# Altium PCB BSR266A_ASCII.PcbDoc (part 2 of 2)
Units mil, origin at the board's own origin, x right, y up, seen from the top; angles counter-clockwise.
Board outline 1624.02 x 1771.65 mil, 4 copper layers (Top Layer, GND 01, GND 02, Bottom Layer), stack 60.4 mil thick; 39 components, 9 nets, 52 pads, 271 vias.
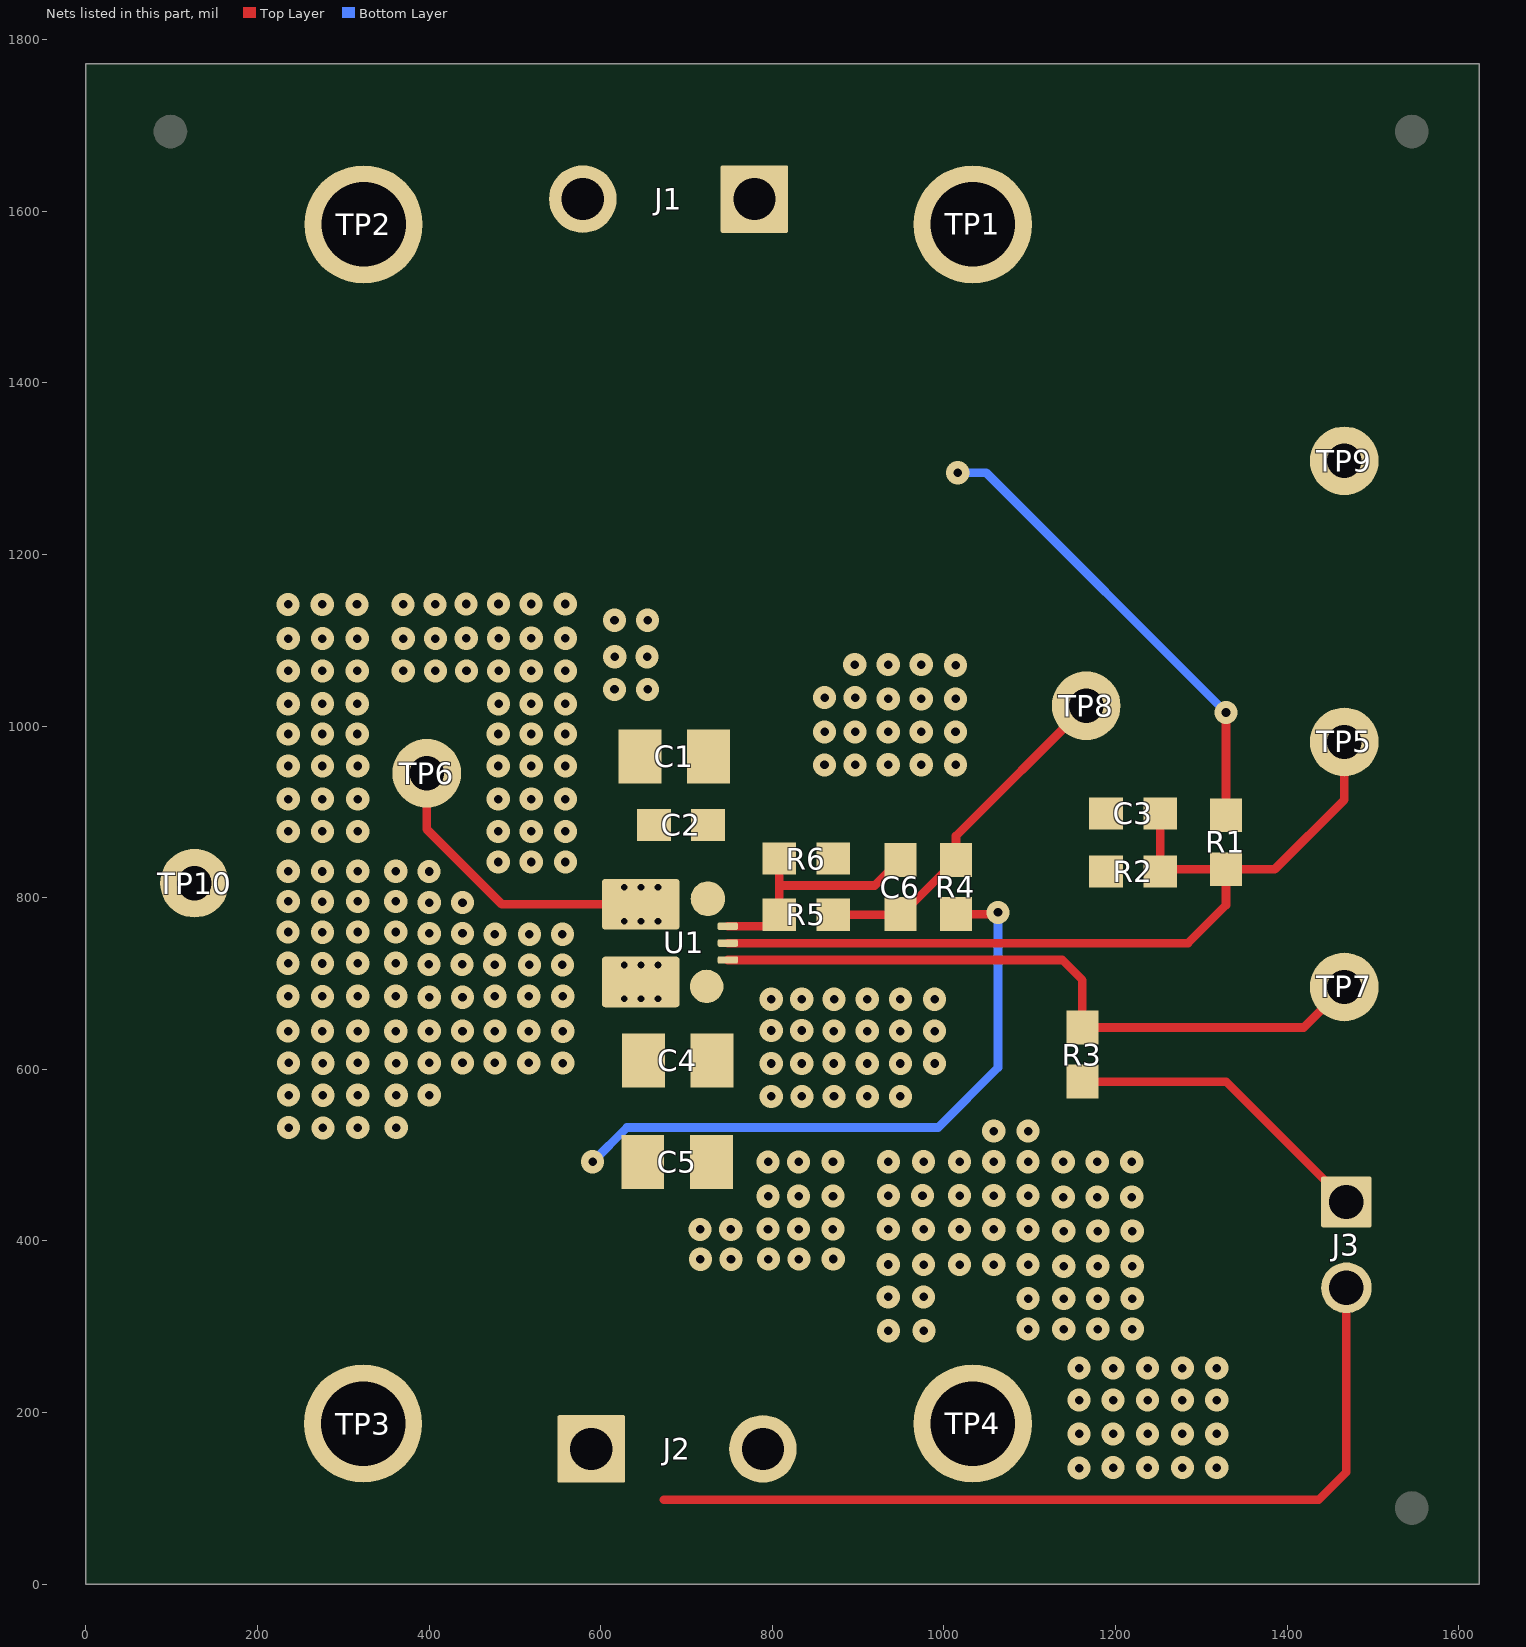
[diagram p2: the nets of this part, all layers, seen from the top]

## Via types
v1: diameter 27, hole 10, Top Layer to Bottom Layer, 259 vias
v2: diameter 19.68, hole 7.87, Top Layer to Bottom Layer, 12 vias

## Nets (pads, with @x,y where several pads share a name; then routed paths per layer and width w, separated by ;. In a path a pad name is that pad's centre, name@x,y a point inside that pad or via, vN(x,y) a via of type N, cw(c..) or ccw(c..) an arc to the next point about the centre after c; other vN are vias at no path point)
EN: C3.1 R1.1 R2.2 TP5.1 U1.6 | length 1025
  Top Layer w10: U1.6@748.03,747.03 1284.45,747.03 1328.68,791.27 R1.1@1328.68,833.01 ; C3.1@1251.97,898.2 R2.2@1251.97,830.56 1254.42,833.01 R1.1@1328.68,833.01 ; TP5.1@1466.54,981.48 1466.54,913.96 1385.59,833.01 R1.1@1328.68,833.01
FB: C6.2 R5.1 R6.2 U1.7 | length 295.7
  Top Layer w10: U1.7@748.03,766.71 794.67,766.71 R5.1@808.05,780.09 808.05,814.15 ; R5.1@799.97,766.71 R5.1@808.05,774.78 ; R6.2@808.05,845.47 808.05,814.15 ; C6.2@949.12,843.81 919.46,814.15 808.05,814.15
GND: C1.2 C2.2 C3.2 C4.2 C5.2 J1.2 J2.2 R2.1 R6.1 TP2.1 TP4.1 TP9.1 TP10.1 U1.4
  other v1: 1157.46,135.1 1197.18,135.65 1237.29,135.65 1277.84,135.65 1317.96,135.65 1157.46,175.02 1197.18,175.02 1237.29,175.02 1277.84,175.02 1317.96,175.02 1157.46,214.39 1197.18,214.39 1237.29,214.39 1277.84,214.39 1317.96,214.39 1157.46,251.67 1197.18,251.67 1237.29,251.67 1277.84,251.67 1317.96,251.67 935.3,295.28 976.58,295.28 1098.13,297.07 1139.52,297.07 1179.24,297.07 1219.36,297.07 1098.13,332.68 1139.52,332.68 1179.24,332.68 1219.36,332.68 935.04,334.65 976.32,334.65 1139.52,370.39 1179.24,370.39 1219.36,370.39 935.04,372.39 976.32,372.36 1018.29,372.36 1058.01,372.36 1098.13,372.36 716.13,378.49 751.8,378.49 795.31,378.74 830.99,378.74 871,378.82 1139.52,411.42 1179.24,411.42 1219.36,411.42 715.75,413.39 751.42,413.39 976.32,413.39 1018.29,413.39 1058.01,413.39 1098.13,413.39 794.93,413.64 830.6,413.64 870.61,413.72 935.04,413.69 1138.96,451.02 1178.69,451.02 1218.8,451.02 794.98,452.04 830.6,452.04 870.66,452.12 935.3,452.76 975.03,452.76 1018.29,452.76 1058.01,452.76 1098.13,452.76 794.98,492.04 830.6,492.04 870.66,492.13 935.3,492.13 976.32,492.13 1018.29,492.13 1058.01,492.13 1098.13,492.13 1138.96,492.04 1178.69,492.04 1218.8,492.04 1058.01,527.83 1098.13,527.83 236.14,531.96 276.12,531.69 316.69,531.96 361.57,531.96 798.69,568.36 834.37,568.36 871.81,568.36 910.7,568.36 949.18,568.36 236.14,569.87 276.12,569.59 316.69,569.87 361.57,569.7 400.07,569.87 236.14,607.33 276.12,607.06 316.69,607.33 361.57,607.17 400.07,607.33 438.83,607.33 476.63,607.33 516.06,607.33 555.68,607.17 798.64,606.72 834.31,606.72 871.76,606.72 910.65,606.72 949.18,606.72 989.17,606.72 235.61,644.49 275.59,644.21 316.69,644.49 361.04,644.32 400.07,644.49 438.83,644.49 476.63,644.49 516.06,644.49 555.68,644.32 871.76,644.49 910.65,644.49 949.18,644.49 989.17,644.49 798.69,645.12 834.31,645.12 798.69,681.58 834.31,681.58 871.94,681.58 910.65,681.58 949.18,681.58 989.17,681.58 400.07,683.88 438.83,683.88 235.61,685.16 275.59,684.89 316.69,685.16 361.04,685.16 476.63,685.16 516.06,685.16 555.68,685.16 399.71,722.2 438.46,722.2 476.27,721.68 516.79,721.68 555.32,721.68 235.61,723.47 275.59,723.2 316.69,723.47 361.04,723.47 476.63,757.34 516.79,757.34 555.32,757.34 400.07,758.25 438.83,758.25 235.61,759.94 275.59,759.67 316.69,759.94 361.04,759.94 400.07,794.27 438.83,794.27 275.59,795.28 235.81,795.55 316.69,795.55 361.04,795.55 235.81,830.78 275.59,830.5 316.69,830.78 361.04,830.78 399.93,830.5 480.44,841.52 518.97,841.52 558.78,841.52 235.81,877.17 275.59,877.17 316.69,877.17 480.44,877.17 518.97,877.17 558.78,877.17 235.81,914.91 275.59,914.91 316.69,914.91 480.55,914.91 518.97,914.91 558.78,914.91 235.81,953.44 275.59,953.44 316.69,953.44 480.55,953.44 518.97,953.44 558.78,953.44 860.8,954.72 896.47,954.72 935.04,954.87 973.59,954.87 1013.52,954.87 235.81,990.72 275.59,990.72 316.11,990.72 480.55,990.72 518.97,990.72 558.78,990.72 860.85,993.13 896.47,993.13 934.99,993.23 973.54,993.23 1013.47,993.23 235.81,1025.99 275.59,1025.99 316.11,1025.99 480.99,1025.99 518.97,1025.81 558.78,1025.81 935.04,1031.63 973.54,1031.63 1013.52,1031.63 860.85,1033.13 896.47,1033.13 616.05,1042.66 654.58,1042.66 235.81,1064.25 275.59,1064.25 316.11,1064.25 369.76,1064.25 407.2,1064.25 443.55,1064.25 480.99,1064.25 518.97,1064.25 558.78,1064.25 1013.52,1070.87 896.11,1071.64 935.04,1071.64 973.54,1071.64 616.21,1080.76 654.02,1080.76 235.81,1101.84 275.59,1101.84 316.11,1101.84 369.76,1101.84 407.2,1101.84 443.19,1102.36 480.99,1102.36 518.97,1102.36 558.78,1102.36 616.05,1123.31 654.58,1123.31 235.61,1141.73 275.39,1141.73 315.91,1141.73 369.56,1141.73 407,1141.73 442.99,1142.25 480.79,1142.25 518.77,1142.25 558.58,1142.25
NetC6_1: C6.1 R4.1 R5.2 TP8.1 | length 412
  Top Layer w10: R5.2@871.04,780.09 948.38,780.09 C6.1@949.12,780.82 951,780.82 R4.1@1014,843.81 1014,871.83 TP8.1@1165.78,1023.62
NetJ3_1: J3.1 R3.2 | length 365.8
  Top Layer w10: R3.2@1161.42,585.62 1328.68,585.62 J3.1@1469.04,445.27
PG: R3.1 TP7.1 U1.5 | length 803.1
  Top Layer w10: U1.5@748.03,727.34 1137.99,727.34 1161.42,703.92 R3.1@1161.42,648.61 1419.29,648.61 TP7.1@1466.54,695.86
SW: TP6.1 U1.2 | length 351
  Top Layer w10: TP6.1@397.19,945 397.19,879.68 484.57,792.3 U1.2@646.65,792.3
  other v2: 627.36,772.62 647.05,772.62 666.73,772.62 627.36,811.99 647.05,811.99 666.73,811.99
Vin: C1.1 C2.1 J1.1 R1.2 TP1.1 U1.1 | length 548.2
  Top Layer w10: R1.2@1328.68,896 1328.68,1015.72 v1(1328.74,1015.77)
  Bottom Layer w10: v1(1016.06,1295.19) 1049.33,1295.19 v1(1328.74,1015.77)
VOUT: C4.1 C5.1 J2.1 J3.2 R4.2 TP3.1 U1.3 | length 1772.1
  Top Layer w10: 673.62,98.43 1437.01,98.43 1469.04,130.45 J3.2@1469.04,345.27 ; R4.2@1014,780.82 1061.05,780.82 v1(1062.99,782.77)
  Bottom Layer w10: v1(590.55,492.13) 630.55,532.13 993.24,532.13 1062.99,601.87 v1(1062.99,782.77)
  other v2: 627.36,682.07 647.05,682.07 666.73,682.07 627.36,721.44 647.05,721.44 666.73,721.44
pads on no net: FID1.1 FID2.1 FID3.1 LBL1.0 SH-JP1.0

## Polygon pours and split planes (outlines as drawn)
GND on Top Layer "TOP_LAYER_GND_P106" (solid, remove dead copper, pour order 106): 0,1771.65 1624.02,1771.65 1624.02,0 0,0
Vin on Top Layer "TOP_LAYER_VIN_P076" (solid, remove dead copper, pour order 76): 688.98,1771.65 691.82,1768.81 691.82,757.34 725.22,757.34 827.04,859.16 827.04,1037.1 1181.1,1391.16 1181.1,1771.65 692.91,1771.65
VOUT on Top Layer "TOP_LAYER_VOUT_P074" (solid, remove dead copper, pour order 74): 593.49,732.16 594.17,731.47 692.16,731.47 692.16,0 216.54,0 216.54,324.8 447.83,556.1 594.49,556.1 594.49,730.94 594.21,731.21
GND on Bottom Layer "BOTTOM_LAYER_GND_P100" (solid, remove dead copper, pour order 100): 0,1771.65 1624.02,1771.65 1624.02,0 0,0
VOUT on Bottom Layer "BOTTOM_LAYER_VOUT_P044" (solid, remove dead copper, pour order 44): 600.92,730.49 601.91,731.47 692.16,731.47 692.16,672.22 691.56,672.82 601.29,672.82 601.29,730.12
SW on Bottom Layer "BOTTOM_LAYER_SW_P036" (solid, remove dead copper, pour order 36): 602.74,821.83 692.52,821.83 692.52,761.14 691.09,762.58 600.56,762.58 600.56,821.01 603.1,823.55
GND on GND 02 "GND_02_GND_P102" (solid, remove dead copper, pour order 102): 0,1771.65 1624.02,1771.65 1624.02,0 0,0
GND on GND 01 "GND_01_GND_P104" (solid, remove dead copper, pour order 104): 0,1771.65 1624.02,1771.65 1624.02,0 1614.17,-9.84 0,-9.84

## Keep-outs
Keep-Out Layer:
  text ".Layer_Name" at 577,-858.49 h60

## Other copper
Top Layer:
  text ".Layer_Name" at 577,-858.49 h60
Bottom Layer:
  text ".Layer_Name" at 577,-858.49 h60

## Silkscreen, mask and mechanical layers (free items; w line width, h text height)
Top Overlay:
  lines w3.97: 580.2,836.18 580.64,836.61 ; 599.47,836.61 600.2,837.34
  lines w6: 580.2,836.18 580.2,659.45 604.92,659.45 ; 580.64,836.61 599.47,836.61 ; 600.2,837.34 600.2,1013.78 767.72,1013.78 767.72,885.83 909.03,885.83 910.26,741.88 775.77,742.43 775.77,561.02 606.45,561.02 606.45,659.45
  text "BSR266E1" at 1151.57,1683.07 h80
  text "GND" at 285.43,1446.85 h40
  text "VIN" at 1004.07,1446.85 h40
  text "Solution Size" at 993.53,1335.9 h30
  text "=65 sq mm" at 1077.86,1287.19 h30
  text "GND" at 1427.17,1213.68 h40
  text "BODE" at 1201.77,1038.2 h40
  text "EN" at 1423.92,880.55 h40
  text "SW" at 357.04,846.77 h40
  text "GND" at 87.41,721.44 h40
  text "PG" at 1427.17,590.55 h40
  text "PG_Pull_Up" at 1322.98,500.71 h40
  text "VOUT" at 275.59,58.07 h40
  text "GND" at 994.09,58.07 h40
  text ".Layer_Name" at 577,-858.49 h40
Bottom Overlay:
  text ".Layer_Name" at 577,-858.49 h60
Top Paste:
  text ".Layer_Name" at 577,-858.49 h60
Bottom Paste:
  text ".Layer_Name" at 577,-858.49 h60
Top Solder:
  text ".Layer_Name" at 577,-858.49 h60
  text ".Layer_Name" at 577,-858.49 h60
Bottom Solder:
  text ".Layer_Name" at 577,-858.49 h60
Drill Guide:
  text ".Layer_Name" at 577,-858.49 h60
M1 Board Outline:
  the board outline again, w10
  text ".Layer_Name" at 577,-858.49 h60
M2 Board Dimensions:
  rectangle: 0,-275 125,-150
  rectangle: 125,-400 500,-275
  lines w7: 0,-275 1000,-275 ; 125,-400 125,-150 ; 250,-400 250,-150 ; 500,-400 500,-150 ; 750,-400 750,-150 ; 0,-400 1000,-400 1000,-150 0,-150 0,-400
  text ".Layer_Name" at 577,-858.49 h60
M3 3D STEP Top:
  text ".Layer_Name" at 577,-858.49 h60
M4 3D STEP Bottom:
  text ".Layer_Name" at 577,-858.49 h60
M5 Assembly Top:
  lines w10: -292,-930.17 6308,-930.17 ; -292,-726.83 6310,-726.83 ; -292,-523.5 -292,-1133.5 3713,-1133.5 6310,-1133.5 6310,-523.5 -291.5,-523.5 -291.5,-1133.5 1284,-1133.5 ; 2173,-1133.5 2173,-523.5 ; 3440,-726.83 3440,-523.5 ; 4280,-726.83 4280,-523.5 ; 4902,-1140 4902,-937.17
  text "COMPONENTS MARKED 'DNP' SHOULD NOT BE POPULATED." at 1153.5,-318.5 h60
  text "ASSEMBLY VARIANT:" at 1153,-434 h60
  text ".VariantName" at 2189,-434 h60
  text "PCB VIEWED FROM TOP SIDE" at -228.5,-655.67 h60
  text "BOARD #:" at 2248,-655.67 h60
  text ".PRJ_Number" at 2793.5,-655.67 h60
  text "REV:" at 3638,-655.67 h60
  text ".PCB_Rev" at 3929.5,-655.67 h60
  text "SVN REV:" at 4476,-655.67 h60
  text ".VersionControl_RevNumber" at 4982,-655.67 h60
  text "TID #:" at 2248,-859 h60
  text ".TID" at 2793.5,-859 h60
  text "PLOT NAME =" at -228.5,-1064.34 h60
  text ".plot_File_Name" at 577,-1064.34 h60
  text "GENERATED    :" at 2250,-1064.34 h60
  text ".Print_Date" at 3119.5,-1064.34 h60
  text ".Print_Time" at 3848.5,-1064.34 h60
  text "TEXAS INSTRUMENTS" at 5113,-1064.34 h60
M6 Assembly Bottom:
  lines w10: -292.5,-727.33 6309.5,-727.33 ; -290.5,-930.67 6309.5,-930.67 ; 1115.5,-1140.5 1115.5,-937.67 ; 1737.5,-727.33 1737.5,-524 ; 2577.5,-727.33 2577.5,-524 ; 3844.5,-1134 3844.5,-524 ; 4733.5,-1134 6309,-1134 6309,-524 -292.5,-524 -292.5,-1134 2304.5,-1134 6309.5,-1134 6309.5,-524
  text "COMPONENTS MARKED 'DNP' SHOULD NOT BE POPULATED." at 6102,-318 h60
  text ".VariantName" at 5058,-434 h60
  text "ASSEMBLY VARIANT:" at 6097,-434 h60
  text ".VersionControl_RevNumber" at 1035.5,-656.17 h60
  text "SVN REV:" at 1541.5,-656.17 h60
  text ".PCB_Rev" at 2088,-656.17 h60
  text "REV:" at 2379.5,-656.17 h60
  text ".PRJ_Number" at 3224,-656.17 h60
  text "BOARD #:" at 3769.5,-656.17 h60
  text "PCB VIEWED FROM BOTTOM SIDE" at 6246,-656.17 h60
  text ".TID" at 3224,-859.5 h60
  text "TID #:" at 3769.5,-859.5 h60
  text "TEXAS INSTRUMENTS" at 904.5,-1064.84 h60
  text ".Print_Time" at 2169,-1064.84 h60
  text ".Print_Date" at 2898,-1064.84 h60
  text "GENERATED    :" at 3767.5,-1064.84 h60
  text ".plot_File_Name" at 5440.5,-1064.84 h60
  text "PLOT NAME =" at 6246,-1064.84 h60
M9 Title Sheet:
  lines w10: -491.5,1041.5 -291.5,1041.5 ; -491.5,3416.5 -291.5,3416.5 ; -491.5,5791.5 -291.5,5791.5 ; 2008.5,-1333.5 2008.5,-1133.5 ; 2008.5,7966.5 2008.5,8166.5 ; 4508.5,-1333.5 4508.5,-1133.5 ; 4508.5,7966.5 4508.5,8166.5 ; 6321,-1133.5 6321,-523.5 11303.5,-523.5 ; 7008.5,-1333.5 7008.5,-1133.5 ; 7008.5,7966.5 7008.5,8166.5 ; 9508.5,-1333.5 9508.5,-1133.5 ; 9508.5,7966.5 9508.5,8166.5 ; 11303.5,-1133.5 11303.5,-523.5 ; 11303.5,-823.5 14303.5,-823.5 ; 11303.5,-223.5 14303.5,-223.5 ; 11304.5,370.5 14304.5,370.5 ; 12008.5,-1333.5 12008.5,-1133.5 ; 12008.5,7966.5 12008.5,8166.5 ; 12808.5,-1123.5 12808.5,-523.5 ; 14303.5,-523.5 11303.5,-523.5 ; 14303.5,76.5 11303.5,76.5 ; 14308.5,66.5 14308.5,-1133.5 ; 14308.5,871 11304.5,871 11303.5,871 11303.5,370.5 11303.5,76.5 ; 14308.5,1041.5 14508.5,1041.5 ; 14308.5,3416.5 14508.5,3416.5 ; 14308.5,5791.5 14508.5,5791.5 ; 11303.5,-523.5 11303.5,76.5 ; 14308.5,-1133.5 14308.5,7966.5 -291.5,7966.5 -291.5,-1133.5 14308.5,-1133.5 ; -491.5,-1333.5 -491.5,8166.5 14508.5,8166.5 14508.5,-1333.5 -491.5,-1333.5
  text "1" at 739.84,8036.5 h70
  text "2" at 3235.5,8036.5 h70
  text "3" at 5724.84,8036.5 h70
  text "4" at 8231.51,8036.5 h70
  text "5" at 10730.5,8036.5 h70
  text "6" at 13235.5,8036.5 h70
  text "A" at -416.5,6893.5 h70
  text "A" at 14383.5,6893.5 h70
  text "B" at -416.5,4513.5 h70
  text "B" at 14383.5,4513.5 h70
  text "C" at -416.5,2138.5 h70
  text "C" at 14383.5,2138.5 h70
  text "PROJECT TITLE:" at 11343.5,277.5 h45
  text ".PRJ_Title" at 11393.5,144.17 h70
  text "DESIGNED FOR:" at 11343.5,-23.5 h45
  text ".PRJ_Customer" at 11393.5,-163.5 h70
  text "D" at -416.5,-231.5 h70
  text "D" at 14383.5,-231.5 h70
  text "FILE NAME:" at 11343.5,-323.5 h45
  text ".PCB_File_Name_No_Path" at 11393.5,-443.5 h70
  text "Texas Instruments (TI) and/or its licensors do not warrant the accuracy or completeness of this specification" at 6374,-605.34 h45
  text "ENGINEER:" at 11343.5,-613.5 h45
  text "LAYOUT BY:" at 12848.5,-613.5 h45
  text "or any information contained therein. TI and/or its licensors do not warrant that this design will meet" at 6329.01,-718 h45
  text ".PRJ_Engineer" at 11393.5,-768.49 h70
  text ".PCB_Layout" at 12899,-768.49 h70
  text "the specifications, will be suitable for your application or fit for any particular purpose, or will operate in" at 6329.01,-830.67 h45
  text ".Layer_Name" at 577,-858.49 h60
  text "ALTIUM DESIGNER VERSION:" at 12848.5,-923.5 h45
  text "an implementation. TI and/or its licensors do not warrant that the design is production worthy. You should" at 6329.01,-943.33 h45
  text "completely validate and test your design implementation to confirm the system functionality for your application." at 6374,-1056 h45
  text ".print_Scale" at 11393.5,-1056.83 h70
  text ".Application_BuildNumber" at 12899,-1056.83 h70
  text "1" at 739.84,-1263.5 h70
  text "2" at 3235.5,-1263.5 h70
  text "3" at 5724.84,-1263.5 h70
  text "4" at 8231.51,-1263.5 h70
  text "5" at 10730.5,-1263.5 h70
  text "6" at 13235.5,-1263.5 h70
M10 Fab Notes:
  drawing of 189 lines, arcs and shapes, not listed
  text "DESIGN INFORMATION" at 12382.02,6356.17 h60
  text "MIN. TRACK WIDTH:" at 11737.46,6224.05 h60
  text "8" at 12833.7,6224.05 h60
  text "MIL" at 12988.46,6224.05 h60
  text "MIN. CLEARANCE:" at 11737.46,6099.92 h60
  text "0.2" at 12773.7,6099.93 h60
  text "mm" at 12988.46,6099.92 h60
  text "MIN. VIA PAD SIZE:" at 11737.46,5975.8 h60
  text "24" at 12803.71,5975.8 h60
  text "MIL" at 12988.46,5975.8 h60
  text "0.05mm (2MIL)" at 12432.46,5845.9 h60
  text "MINIMUM ANNULAR RING" at 11408.23,5837.67 h60
  text "EXTERNAL" at 13140.46,5837.67 h60
  text "PER" at 11608.23,5727.55 h60
  text "IPC-D-275 CLASS 2 LEVEL C" at 11828.23,5727.54 h60
  text "MIL, HOLES" at 13316.46,5627.07 h60
  text "+/-" at 12924,5618.48 h60
  text "+/-" at 13778,5618.48 h60
  text "REGISTRATION TOLERANCES:" at 11408.23,5617.42 h60
  text "METAL" at 12608,5617.42 h60
  text "5" at 13184.2,5617.42 h60
  text "3" at 14017.2,5617.42 h60
  text "MIL" at 14133.46,5617.42 h60
  text "HOLE SIZE TOLERANCE (UNLESS OTHERWISE SPECIFIED):" at 11408.23,5519.1 h60
  text "+/-" at 13778,5516.23 h60
  text "3" at 14017.2,5515.17 h60
  text "MIL" at 14133.46,5515.17 h60
  text "MATERIAL:" at 11333.46,5377.52 h60
  text "FR-4 High Tg" at 12319.9,5249 h60
  text "X" at 12175.46,5241.01 h60
  text "FR-408" at 11754.46,5236.49 h60
  text "OTHER" at 13242.46,5236.49 h60
  text "62 MIL (1.6mm) +/-10%" at 12074.56,5093.46 h60
  text "X" at 11954.46,5091.01 h60
  text "THICKNESS:" at 11408.23,5085.24 h60
  text "OTHER" at 13359.46,5085.24 h60
  text "TOLERANCE:" at 11408.23,4946.92 h60
  text "X" at 12256.46,4946.92 h60
  text "ANSI IPC-6012 TYPE 3 CLASS 2" at 12434.48,4946.92 h60
  text "OTHER +/-" at 12434.46,4802.73 h60
  text "BOW & TWIST:" at 11408.23,4657.54 h60
  text "X" at 12256.46,4657.54 h60
  text "ANSI IPC-6012 TYPE 3 CLASS 2" at 12434.48,4657.54 h60
  text "OTHER +/-" at 12434.46,4510.85 h60
  text "DRILLING:" at 11333.46,4380.23 h60
  text "NC_DRILL FILES" at 13094.46,4275.04 h60
  text "REFERENCE:" at 11408.23,4271.1 h60
  text "X" at 12065.46,4271.01 h60
  text "AS SHOWN" at 12243.46,4271.1 h60
  text "X" at 12966.46,4271.1 h60
  text "OTHER" at 13392.46,4128.85 h60
  text "PTH COPPER THICKNESS:" at 11407.91,4125.32 h60
  text "X" at 12547.14,4125.32 h60
  text "20-30 um" at 12675.14,4125.32 h60
  text "BOARD FINISH:" at 11333.46,3977.73 h60
  text "SILKSCREEN:" at 11488.68,3867.6 h60
  text "X" at 12446.46,3867.6 h60
  text "TOP" at 12563.46,3867.6 h60
  text "X" at 12956.46,3867.6 h60
  text "BOTTOM" at 13074.46,3867.6 h60
  text "SILKSCREEN COLOR:" at 11488.68,3712.41 h60
  text "X" at 12445.46,3712.41 h60
  text "WHITE" at 12563.46,3712.41 h60
  text "OTHER" at 13074.46,3712.41 h60
  text "X" at 12576.46,3568.96 h60
  text "GREEN" at 12694.46,3568.96 h60
  text "OTHER" at 13312.46,3568.96 h60
  text "SOLDER RESIST COLOR:" at 11488.68,3562.1 h60
  text "X" at 12576.46,3414.71 h60
  text "MATTE" at 12694.46,3414.71 h60
  text "SEMI-GLOSS" at 13312,3414.07 h60
  text "IMMERSION GOLD (ENIG)" at 12394.46,3241.94 h60
  text "ENEPIG" at 13732,3234.72 h60
  text "SURFACE FINISH:" at 11333.46,3233.72 h60
  text "X" at 12216.46,3233.72 h60
  text "IMM. TIN/SILVER OR EQUIV" at 11663,3096.4 h60
  text "OTHER" at 13094.46,3092.47 h60
  text "ARRAY/PANEL:" at 11333.46,2937.09 h60
  text "CUT AND TRIM PER M1 BOARD OUTLINE" at 12394.46,2928.87 h60
  text "N.C. ROUTE" at 12394.46,2792.9 h60
  text "X" at 13082.46,2792.9 h60
  text "V. SCORE" at 13260.46,2792.9 h60
  text "CERTIFICATION:" at 11333.46,2663.77 h60
  text "MATERIALS AND WORKMANSHIP FOR ALL PCBS" at 12058.46,2663.77 h60
  text "TO MEET OR EXCEED THE REQUIREMENTS OF:" at 12058.46,2569.71 h60
  text "X" at 11695.97,2441.08 h60
  text "ANSI IPC-A-600F CLASS ->" at 11823.96,2441.08 h60
  text "X" at 13471.97,2441.08 h60
  text "2" at 13581.96,2441.08 h60
  text "1" at 13266.96,2439.58 h60
  text "3" at 13935.96,2439.58 h60
  text "X" at 12507.97,2293.39 h60
  text "RoHS" at 12635.96,2293.39 h60
  text "OTHER" at 13280.36,2293.39 h60
  text "PER ORDER" at 13677.42,2293.39 h60
  text "ALL BOARDS MUST MEET OR EXCEED UL94-V0 REQUIREMENTS." at 11361,2139.57 h60
  text "PCB MUST BEAR THE UL94V-0 UL REGISTERED MATERIAL ID NUMBER" at 11361,2023.5 h60
  text "ADDITIONAL REQUIREMENTS:" at 11333.46,1854.08 h60
  text "MICROSECTION:" at 11408.23,1746.95 h60
  text "YES" at 12313.96,1746.95 h60
  text "REQUIRED" at 13175.46,1602.62 h60
  text "BARE BOARD ELEC. TEST:" at 11408.23,1599.76 h60
  text "NONE" at 12713.96,1599.76 h60
  text "X" at 13057.46,1599.76 h60
  text "PER ORDER" at 13767.46,1599.76 h60
  text "XX MIL VIAS REQUIRE NON-CONDUCTIVE FILL AND PLANARIZE" at 11576.38,1394.82 h59
  text "XX MIL VIAS REQUIRE CONDUCTIVE FILL AND PLANARIZE" at 11584.38,1290.84 h60
  text "OUTER XX MIL TRACES REQUIRE 50 OHM SINGLE-ENDED IMPEDANCE" at 11583.39,1127.46 h58
  text "LAYER 2 & 3 (INNER LAYERS) XX MIL WIDE, XX MIL SPACE / TRACES REQUIRE 100 OHM DIFFERENTIAL IMPEDANCE" at 11575.39,891.74 h60
  text ".Layer_Name" at 577,-858.49 h60
M11 Gerber Information:
  lines w10: -292,-930.17 6308,-930.17 ; -292,-726.83 6310,-726.83 ; -292,-523.5 -292,-1133.5 3713,-1133.5 6310,-1133.5 6310,-523.5 -291.5,-523.5 -291.5,-1133.5 1284,-1133.5 ; 2173,-1133.5 2173,-523.5 ; 3440,-726.83 3440,-523.5 ; 4280,-726.83 4280,-523.5 ; 4902,-1140 4902,-937.17
  text "ALL ARTWORK VIEWED FROM TOP SIDE" at -228.5,-655.67 h60
  text "BOARD #:" at 2248,-655.67 h60
  text ".PRJ_Number" at 2793.5,-655.67 h60
  text "REV:" at 3638,-655.67 h60
  text ".PCB_Rev" at 3929.5,-655.67 h60
  text "SVN REV:" at 4476,-655.67 h60
  text ".VersionControl_RevNumber" at 4982,-655.67 h60
  text "LAYER NAME =" at -228.5,-858.49 h60
  text "TID #:" at 2248,-859 h60
  text ".TID" at 2793.5,-859 h60
  text "PLOT NAME =" at -228.5,-1064.34 h60
  text ".plot_File_Name" at 577,-1064.34 h60
  text "GENERATED    :" at 2250,-1064.34 h60
  text ".Print_Date" at 3119.5,-1064.34 h60
  text ".Print_Time" at 3848.5,-1064.34 h60
  text "TEXAS INSTRUMENTS" at 5113,-1064.34 h60
M12 Stackup:
  drawing of 269 lines, arcs and shapes, not listed
  text "Layer" at 1906.14,975.12 h60
  text "Name" at 2316.06,975.12 h60
  text "Material" at 3175.82,975.12 h60
  text "Thickness" at 4035.59,975.12 h60
  text "Constant" at 4685.43,975.12 h60
  text "Board Layer Stack" at 5255.29,975.12 h60
  text "Top Overlay" at 2316.06,855.12 h60
  text "Top Solder" at 2316.06,735.12 h60
  text "Solder Resist" at 3175.82,735.12 h60
  text "0.40mil" at 4035.59,735.12 h60
  text "3.5" at 4685.43,735.12 h60
  text "1" at 1906.14,615.12 h60
  text "Top Layer" at 2316.06,615.12 h60
  text "2.80mil" at 4035.59,615.12 h60
  text "Dielectric 1" at 2316.06,495.12 h60
  text "FR-4 High Tg" at 3175.82,495.12 h60
  text "6.00mil" at 4035.59,495.12 h60
  text "4.8" at 4685.43,495.12 h60
  text "2" at 1906.14,375.12 h60
  text "GND 01" at 2316.06,375.12 h60
  text "1.40mil" at 4035.59,375.12 h60
  text "Dielectric 2" at 2316.06,255.12 h60
  text "FR-4 High Tg" at 3175.82,255.12 h60
  text "40.00mil" at 4035.59,255.12 h60
  text "4.8" at 4685.43,255.12 h60
  text "3" at 1906.14,135.12 h60
  text "GND 02" at 2316.06,135.12 h60
  text "1.40mil" at 4035.59,135.12 h60
  text "Dielectric 3" at 2316.06,15.12 h60
  text "FR-4 High Tg" at 3175.82,15.12 h60
  text "6.00mil" at 4035.59,15.12 h60
  text "4.2" at 4685.43,15.12 h60
  text "4" at 1906.14,-104.88 h60
  text "Bottom Layer" at 2316.06,-104.88 h60
  text "2.80mil" at 4035.59,-104.88 h60
  text "Bottom Solder" at 2316.06,-224.88 h60
  text "Solder Resist" at 3175.82,-224.88 h60
  text "0.40mil" at 4035.59,-224.88 h60
  text "3.5" at 4685.43,-224.88 h60
  text ".Layer_Name" at 577,-858.49 h60
M13 Component Bodies Top:
  text ".Layer_Name" at 577,-858.49 h60
M14 Component Bodies Bottom:
  text ".Layer_Name" at 577,-858.49 h60
M15 Courtyards Top:
  text ".Layer_Name" at 577,-858.49 h60
M16 Courtyards Bottom:
  text ".Layer_Name" at 577,-858.49 h60
Drill Drawing:
  lines w10: 1963.88,1616.8 2019.13,1616.8 2019.13,1672.06 1963.88,1672.06 1963.88,1616.8 ; 1963.88,1754.94 1977.69,1754.94 1991.51,1741.12 2005.32,1754.94 2019.13,1754.94 2005.32,1768.75 2019.13,1782.56 2005.32,1782.56 1991.51,1796.38 1977.69,1782.56 1963.88,1782.56 1977.69,1768.75 1963.88,1754.94 ; 1963.88,1865.44 1991.51,1879.26 2019.13,1865.44 2005.32,1893.07 2019.13,1920.7 1991.51,1906.88 1963.88,1920.7 1977.69,1893.07 1963.88,1865.44 ; 1963.88,2045.02 2019.13,2045.02 1991.51,1989.76 1963.88,2045.02 ; 1963.88,2127.9 1977.69,2127.9 1977.69,2114.08 2005.32,2114.08 2005.32,2127.9 2019.13,2127.9 2019.13,2155.52 2005.32,2155.52 2005.32,2169.34 1977.69,2169.34 1977.69,2155.52 1963.88,2155.52 1963.88,2127.9
  lines w12: 1913.79,1579.51 5145.28,1579.51 ; 1913.79,2201.11 5145.28,2201.11 ; 2251.65,1455.19 2251.65,2325.43 ; 2583.65,1455.19 2583.65,2325.43 ; 3220.22,1455.19 3220.22,2325.43 ; 3479.36,1455.19 3479.36,2325.43 ; 3854.52,1455.19 3854.52,2325.43 ; 4578.85,1455.19 4578.85,2325.43 ; 1913.79,1455.19 5145.28,1455.19 5145.28,2325.43 1913.79,2325.43 1913.79,1455.19
  text "Symbol" at 1988.38,2238.4 h72
  text "Quantity" at 2288.95,2238.4 h72
  text "Finished Hole Size" at 2620.95,2238.4 h72
  text "Plated" at 3257.51,2238.4 h72
  text "Hole Type" at 3516.65,2238.4 h72
  text "Drill Layer Pair" at 3891.81,2238.4 h72
  text "Hole Tolerance" at 4616.14,2238.4 h72
  text "12" at 2288.95,2114.08 h60
  text "7.87mil (0.200mm)" at 2620.95,2114.08 h60
  text "PTH" at 3257.51,2114.08 h60
  text "Round" at 3516.65,2114.08 h60
  text "Top Layer - Bottom Layer" at 3891.81,2114.08 h60
  text "259" at 2288.95,1989.76 h60
  text "10.00mil (0.254mm)" at 2620.95,1989.76 h60
  text "PTH" at 3257.51,1989.76 h60
  text "Round" at 3516.65,1989.76 h60
  text "Top Layer - Bottom Layer" at 3891.81,1989.76 h60
  text "8" at 2288.95,1865.44 h60
  text "40.00mil (1.016mm)" at 2620.95,1865.44 h60
  text "PTH" at 3257.51,1865.44 h60
  text "Round" at 3516.65,1865.44 h60
  text "Top Layer - Bottom Layer" at 3891.81,1865.44 h60
  text "4" at 2288.95,1741.12 h60
  text "49.21mil (1.250mm)" at 2620.95,1741.12 h60
  text "PTH" at 3257.51,1741.12 h60
  text "Round" at 3516.65,1741.12 h60
  text "Top Layer - Bottom Layer" at 3891.81,1741.12 h60
  text "4" at 2288.95,1616.8 h60
  text "98.43mil (2.500mm)" at 2620.95,1616.8 h60
  text "PTH" at 3257.51,1616.8 h60
  text "Round" at 3516.65,1616.8 h60
  text "Top Layer - Bottom Layer" at 3891.81,1616.8 h60
  text "287 Total" at 2288.95,1492.48 h60
  text ".Layer_Name" at 577,-858.49 h60
M17 Embedded Cavity:
  text ".Layer_Name" at 577,-858.49 h60
M18 Embedded Assembly:
  text ".Layer_Name" at 577,-858.49 h60
M19 Embedded Keepout:
  text ".Layer_Name" at 577,-858.49 h60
